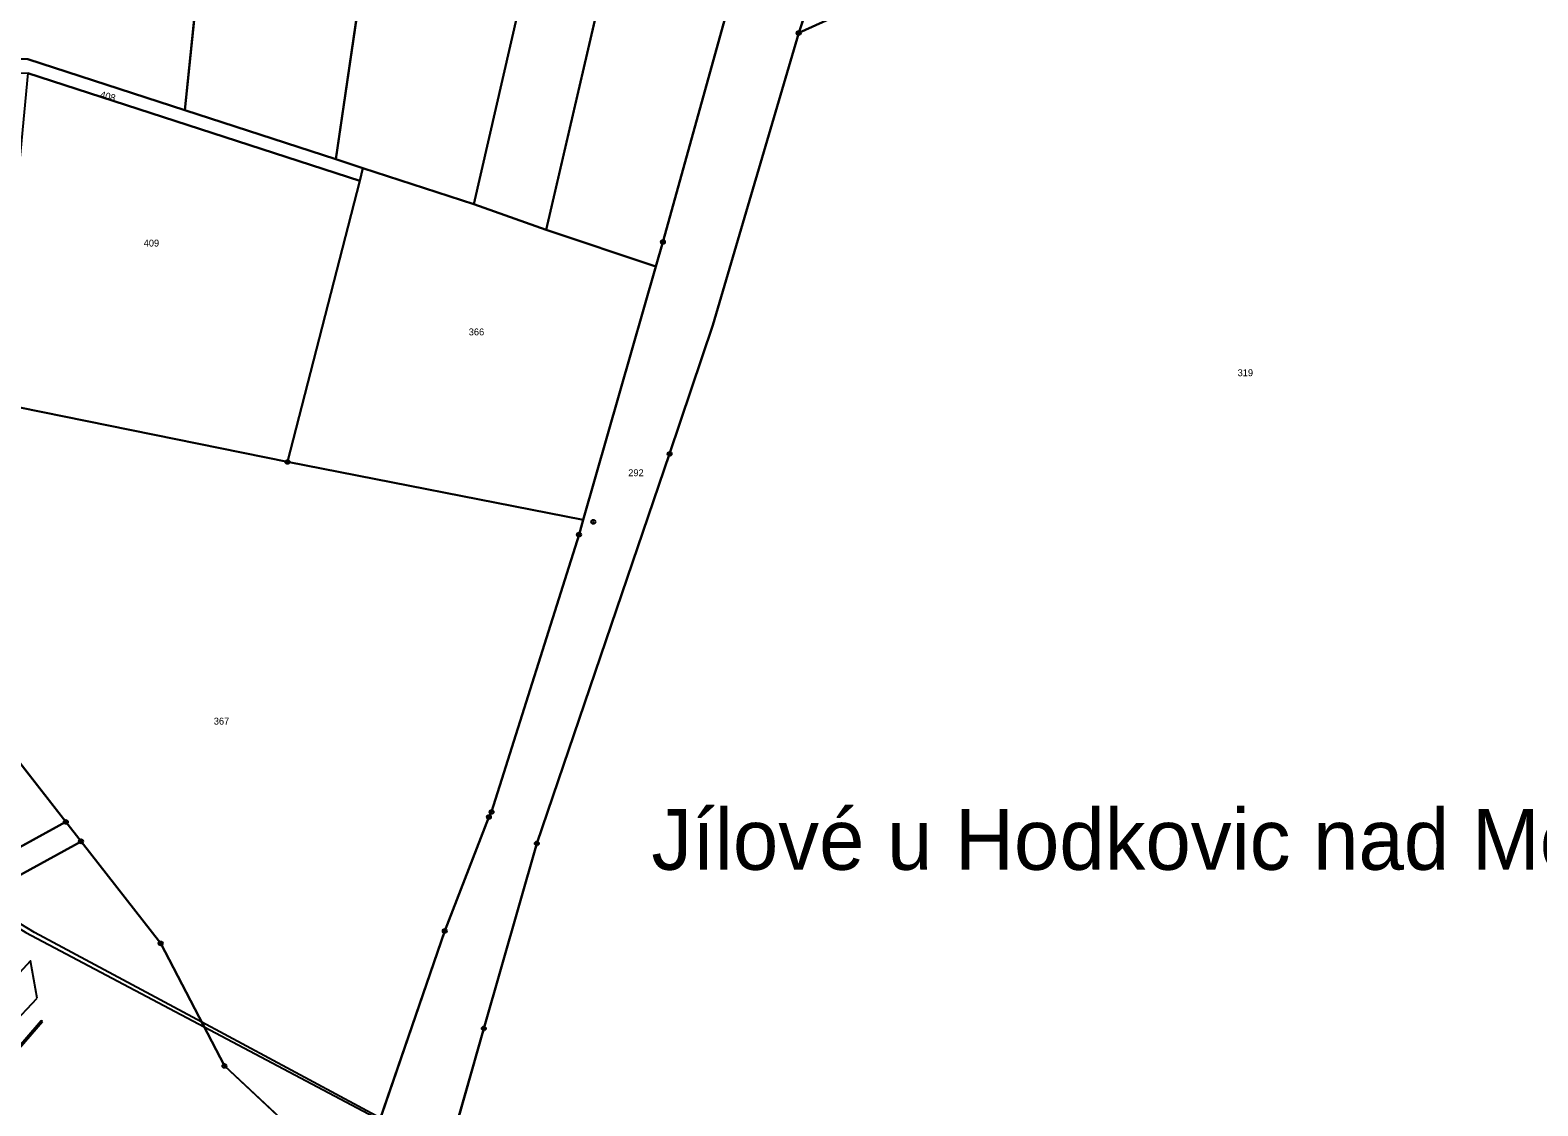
# Model space of a CAD drawing. Extents: x -689422 to -685210, y -987725 to -982160.
# Drawn here: x -686325.7 to -685954.8, y -986505.1 to -986240.3 of the extents above; entities that cross this region are included whole.
import ezdxf

# ---------------------------------------------------------------- set-up
doc = ezdxf.new("R2010")
doc.units = 0
for name, color, linetype in [('KN_Hranice_katastrální území_popis', 7, 'Continuous'), ('KN_Hranice_parcel', 7, 'Continuous'), ('KN_Parcelni cisla', 7, 'Continuous'), ('KN_Polygon parcely', 7, 'Continuous'), ('KN_POZEMKY_ORNA PUDA', 7, 'Continuous'), ('KN_POZEMKY_OSTATNI PLOCHA', 7, 'Continuous'), ('KN_POZEMKY_TTP', 7, 'Continuous'), ('KN_VYUZITI_14_ostatni plocha_dráha', 7, 'Continuous'), ('KN_Věcná břemena k části', 7, 'Continuous'), ('KN_Značky bodu BP', 7, 'Continuous')]:
    doc.layers.add(name, color=color, linetype=linetype)

msp = doc.modelspace()

# ---------------------------------------------------------------- linework, layer by layer
at = {"layer": 'KN_Hranice_parcel'}
for p, q in [((-686095.84, -986117.37), (-686136.64, -986241.02)), ((-686170.02, -986292.49), (-686150.83, -986223.33)), ((-686326.23, -986250.94), (-686244.61, -986277.45)), ((-686250.49, -986272.07), (-686287.61, -986260.01)), ((-686250.49, -986272.07), (-686243.82, -986274.27)), ((-686243.82, -986274.27), (-686244.61, -986277.45)), ((-686216.5, -986283.14), (-686243.82, -986274.27)), ((-686244.61, -986277.45), (-686262.37, -986346.59)), ((-686198.71, -986289.46), (-686216.5, -986283.14)), ((-686171.74, -986298.5), (-686198.71, -986289.46)), ((-686171.74, -986298.5), (-686170.02, -986292.49)), ((-686189.63, -986360.84), (-686171.74, -986298.5)), ((-686333.98, -986332.04), (-686262.37, -986346.59)), ((-686262.37, -986346.59), (-686189.63, -986360.84)), ((-686363.74, -986460.93), (-686316.89, -986435.17)), ((-686316.89, -986435.17), (-686313.16, -986439.96)), ((-686360.85, -986466.19), (-686313.16, -986439.96))]:
    msp.add_line(p, q, dxfattribs=at)
for points in [[(-686287.61, -986260.01), (-686326.21, -986247.46), (-686339.73, -986247.04), (-686323.81, -986199.58), (-686315.21, -986165.49), (-686294.08, -986111.59)], [(-686079.51, -986123.74), (-686120.05, -986233.54), (-686136.64, -986241.02)], [(-686287.61, -986260.01), (-686283.06, -986215.63), (-686271.23, -986167.44), (-686256.35, -986129.53)], [(-686218.39, -986148.4), (-686243.26, -986222.73), (-686250.49, -986272.07)], [(-686182.54, -986165.69), (-686199.37, -986213.85), (-686205.74, -986236.04), (-686216.5, -986283.14)], [(-686166.74, -986173.73), (-686182.84, -986220.79), (-686198.71, -986289.46)], [(-686136.64, -986241.02), (-686157.77, -986312.91), (-686168.38, -986344.61), (-686201.04, -986440.48), (-686214.08, -986486.02), (-686222.26, -986514.82)], [(-686393.73, -986335.43), (-686338.86, -986407.01), (-686316.89, -986435.17)], [(-686189.63, -986360.84), (-686190.67, -986364.48), (-686212.18, -986432.72), (-686212.83, -986433.98), (-686223.69, -986462), (-686245.48, -986525.43)], [(-686313.16, -986439.96), (-686293.56, -986465.08), (-686277.88, -986495.23), (-686245.48, -986525.43)]]:
    msp.add_lwpolyline(points, dxfattribs=at)
at = {"layer": 'KN_Polygon parcely'}
for points in [[(-686256.35, -986129.53), (-686294.08, -986111.59), (-686315.21, -986165.49), (-686323.81, -986199.58), (-686339.73, -986247.04), (-686326.21, -986247.46), (-686287.61, -986260.01), (-686283.06, -986215.63), (-686271.23, -986167.44)], [(-686136.64, -986241.02), (-686120.05, -986233.54), (-686079.51, -986123.74), (-686095.84, -986117.37)], [(-686256.35, -986129.53), (-686271.23, -986167.44), (-686283.06, -986215.63), (-686287.61, -986260.01), (-686250.49, -986272.07), (-686243.26, -986222.73), (-686218.39, -986148.4)], [(-686250.49, -986272.07), (-686243.82, -986274.27), (-686216.5, -986283.14), (-686205.74, -986236.04), (-686199.37, -986213.85), (-686182.54, -986165.69), (-686218.39, -986148.4), (-686243.26, -986222.73)], [(-686205.74, -986236.04), (-686216.5, -986283.14), (-686198.71, -986289.46), (-686182.84, -986220.79), (-686166.74, -986173.73), (-686182.54, -986165.69), (-686199.37, -986213.85)], [(-686166.74, -986173.73), (-686182.84, -986220.79), (-686198.71, -986289.46), (-686171.74, -986298.5), (-686170.02, -986292.49), (-686150.83, -986223.33), (-686158.55, -986214.55), (-686150.96, -986181.1)], [(-686333.98, -986332.04), (-686262.37, -986346.59), (-686244.61, -986277.45), (-686326.23, -986250.94)], [(-686189.63, -986360.84), (-686171.74, -986298.5), (-686198.71, -986289.46), (-686216.5, -986283.14), (-686243.82, -986274.27), (-686244.61, -986277.45), (-686262.37, -986346.59)], [(-686316.89, -986435.17), (-686313.16, -986439.96), (-686293.56, -986465.08), (-686277.88, -986495.23), (-686245.48, -986525.43), (-686223.69, -986462), (-686212.83, -986433.98), (-686212.18, -986432.72), (-686190.67, -986364.48), (-686189.63, -986360.84), (-686262.37, -986346.59), (-686333.98, -986332.04), (-686367.41, -986325.32), (-686369.96, -986327.29), (-686377.99, -986329.38), (-686385.28, -986329.18), (-686393.73, -986335.43), (-686338.86, -986407.01)], [(-686316.89, -986435.17), (-686338.86, -986407.01), (-686393.73, -986335.43), (-686426.63, -986346.03), (-686408.18, -986380.1), (-686363.74, -986460.93)], [(-686360.85, -986466.19), (-686313.16, -986439.96), (-686316.89, -986435.17), (-686363.74, -986460.93)], [(-686268.64, -986613.74), (-686263.17, -986592.87), (-686263.08, -986592.53), (-686245.48, -986525.43), (-686277.88, -986495.23), (-686293.56, -986465.08), (-686313.16, -986439.96), (-686360.85, -986466.19), (-686339.04, -986505.86), (-686281.05, -986622.22)]]:
    msp.add_lwpolyline(points, close=True, dxfattribs=at)
for points in [[(-686222.26, -986514.82), (-686214.08, -986486.02), (-686201.04, -986440.48), (-686168.38, -986344.61), (-686157.77, -986312.91), (-686136.64, -986241.02), (-686095.84, -986117.37)], [(-686328.73, -986199.25), (-686367.73, -986318.6), (-686370.59, -986322.73), (-686377.74, -986326.31), (-686391.61, -986325.86), (-686427.48, -986310.59), (-686454.39, -986299), (-686455.16, -986302.12), (-686392.23, -986329.33), (-686385.28, -986329.18), (-686377.99, -986329.38), (-686369.96, -986327.29), (-686367.41, -986325.32), (-686363.2, -986319.25), (-686341.46, -986252.16), (-686338.9, -986250.37), (-686326.23, -986250.94), (-686244.61, -986277.45), (-686243.82, -986274.27), (-686250.49, -986272.07), (-686287.61, -986260.01), (-686326.21, -986247.46), (-686339.73, -986247.04), (-686323.81, -986199.58)], [(-686150.83, -986223.33), (-686170.02, -986292.49), (-686171.74, -986298.5), (-686189.63, -986360.84), (-686190.67, -986364.48), (-686212.18, -986432.72), (-686212.83, -986433.98), (-686223.69, -986462), (-686245.48, -986525.43), (-686263.08, -986592.53), (-686263.17, -986592.87), (-686268.64, -986613.74), (-686274.17, -986634.95), (-686281.05, -986622.22), (-686281.79, -986632.25), (-686282.71, -986644.54), (-686283.4, -986653.69), (-686317.15, -986737.15), (-686335.84, -986780.59), (-686339.55, -986788.69), (-686341.38, -986792.68), (-686343.41, -986797.11)], [(-686120.05, -986233.54), (-686136.64, -986241.02), (-686157.77, -986312.91), (-686168.38, -986344.61), (-686201.04, -986440.48), (-686214.08, -986486.02), (-686222.26, -986514.82), (-686205.45, -986544.89), (-686181.26, -986594.04), (-686158.28, -986655.04), (-686149.3, -986702.26), (-686138.27, -986745.53), (-686128.64, -986829.8), (-686090.23, -986851.98), (-686084.31, -986849), (-686074.19, -986843.92), (-686054.05, -986878.62), (-686030, -986857.27), (-685896.42, -986709.33)]]:
    msp.add_lwpolyline(points, dxfattribs=at)
at = {"layer": 'KN_POZEMKY_ORNA PUDA'}
for p, q in [((-686287.61, -986260.01), (-686283.06, -986215.63)), ((-686283.06, -986215.63), (-686287.61, -986260.01)), ((-686243.26, -986222.73), (-686250.49, -986272.07)), ((-686250.49, -986272.07), (-686243.26, -986222.73)), ((-686198.71, -986289.46), (-686182.84, -986220.79)), ((-686182.84, -986220.79), (-686198.71, -986289.46)), ((-686150.83, -986223.33), (-686170.02, -986292.49)), ((-686136.64, -986241.02), (-686120.05, -986233.54)), ((-686216.5, -986283.14), (-686205.74, -986236.04)), ((-686205.74, -986236.04), (-686216.5, -986283.14)), ((-686157.77, -986312.91), (-686136.64, -986241.02)), ((-686326.21, -986247.46), (-686287.61, -986260.01)), ((-686287.61, -986260.01), (-686326.21, -986247.46)), ((-686326.23, -986250.94), (-686244.61, -986277.45)), ((-686244.61, -986277.45), (-686326.23, -986250.94)), ((-686250.49, -986272.07), (-686287.61, -986260.01)), ((-686287.61, -986260.01), (-686250.49, -986272.07)), ((-686250.49, -986272.07), (-686243.82, -986274.27)), ((-686243.82, -986274.27), (-686250.49, -986272.07)), ((-686244.61, -986277.45), (-686243.82, -986274.27)), ((-686243.82, -986274.27), (-686244.61, -986277.45)), ((-686243.82, -986274.27), (-686216.5, -986283.14)), ((-686216.5, -986283.14), (-686243.82, -986274.27)), ((-686244.61, -986277.45), (-686262.37, -986346.59)), ((-686262.37, -986346.59), (-686244.61, -986277.45)), ((-686216.5, -986283.14), (-686198.71, -986289.46)), ((-686198.71, -986289.46), (-686216.5, -986283.14)), ((-686171.74, -986298.5), (-686198.71, -986289.46)), ((-686198.71, -986289.46), (-686171.74, -986298.5)), ((-686170.02, -986292.49), (-686171.74, -986298.5)), ((-686171.74, -986298.5), (-686189.63, -986360.84)), ((-686168.38, -986344.61), (-686157.77, -986312.91)), ((-686262.37, -986346.59), (-686333.98, -986332.04)), ((-686333.98, -986332.04), (-686262.37, -986346.59)), ((-686201.04, -986440.48), (-686168.38, -986344.61)), ((-686262.37, -986346.59), (-686189.63, -986360.84)), ((-686189.63, -986360.84), (-686262.37, -986346.59)), ((-686189.63, -986360.84), (-686190.67, -986364.48)), ((-686190.67, -986364.48), (-686212.18, -986432.72)), ((-686338.86, -986407.01), (-686316.89, -986435.17)), ((-686316.89, -986435.17), (-686338.86, -986407.01)), ((-686316.89, -986435.17), (-686363.74, -986460.93)), ((-686363.74, -986460.93), (-686316.89, -986435.17)), ((-686316.89, -986435.17), (-686313.16, -986439.96)), ((-686313.16, -986439.96), (-686316.89, -986435.17)), ((-686212.83, -986433.98), (-686223.69, -986462)), ((-686212.18, -986432.72), (-686212.83, -986433.98)), ((-686360.85, -986466.19), (-686313.16, -986439.96)), ((-686313.16, -986439.96), (-686360.85, -986466.19)), ((-686313.16, -986439.96), (-686293.56, -986465.08)), ((-686293.56, -986465.08), (-686313.16, -986439.96)), ((-686214.08, -986486.02), (-686201.04, -986440.48)), ((-686223.69, -986462), (-686245.48, -986525.43)), ((-686293.56, -986465.08), (-686277.88, -986495.23)), ((-686277.88, -986495.23), (-686293.56, -986465.08)), ((-686222.26, -986514.82), (-686214.08, -986486.02)), ((-686277.88, -986495.23), (-686245.48, -986525.43)), ((-686245.48, -986525.43), (-686277.88, -986495.23))]:
    msp.add_line(p, q, dxfattribs=at)
at = {"layer": 'KN_POZEMKY_OSTATNI PLOCHA'}
for p, q in [((-686095.84, -986117.37), (-686136.64, -986241.02)), ((-686170.02, -986292.49), (-686150.83, -986223.33)), ((-686136.64, -986241.02), (-686157.77, -986312.91)), ((-686171.74, -986298.5), (-686170.02, -986292.49)), ((-686189.63, -986360.84), (-686171.74, -986298.5)), ((-686157.77, -986312.91), (-686168.38, -986344.61)), ((-686168.38, -986344.61), (-686201.04, -986440.48)), ((-686190.67, -986364.48), (-686189.63, -986360.84)), ((-686212.18, -986432.72), (-686190.67, -986364.48)), ((-686223.69, -986462), (-686212.83, -986433.98)), ((-686212.83, -986433.98), (-686212.18, -986432.72)), ((-686201.04, -986440.48), (-686214.08, -986486.02)), ((-686245.48, -986525.43), (-686223.69, -986462)), ((-686214.08, -986486.02), (-686222.26, -986514.82))]:
    msp.add_line(p, q, dxfattribs=at)
at = {"layer": 'KN_POZEMKY_TTP'}
for p, q in [((-686136.64, -986241.02), (-686095.84, -986117.37)), ((-686120.05, -986233.54), (-686136.64, -986241.02))]:
    msp.add_line(p, q, dxfattribs=at)
at = {"layer": 'KN_VYUZITI_14_ostatni plocha_dráha'}
for p, q in [((-686095.84, -986117.37), (-686136.64, -986241.02)), ((-686170.02, -986292.49), (-686150.83, -986223.33)), ((-686136.64, -986241.02), (-686157.77, -986312.91)), ((-686171.74, -986298.5), (-686170.02, -986292.49)), ((-686189.63, -986360.84), (-686171.74, -986298.5)), ((-686157.77, -986312.91), (-686168.38, -986344.61)), ((-686168.38, -986344.61), (-686201.04, -986440.48)), ((-686190.67, -986364.48), (-686189.63, -986360.84)), ((-686212.18, -986432.72), (-686190.67, -986364.48)), ((-686223.69, -986462), (-686212.83, -986433.98)), ((-686212.83, -986433.98), (-686212.18, -986432.72)), ((-686201.04, -986440.48), (-686214.08, -986486.02)), ((-686245.48, -986525.43), (-686223.69, -986462)), ((-686214.08, -986486.02), (-686222.26, -986514.82))]:
    msp.add_line(p, q, dxfattribs=at)
at = {"layer": 'KN_Věcná břemena k části'}
for points in [[(-686282.87, -986485.63), (-686283.47, -986484.47), (-686324.56, -986462.41), (-686382.23, -986427.29), (-686381.47, -986428.69), (-686326.76, -986462.4)], [(-686323.94, -986478.57), (-686325.55, -986469.33), (-686346.58, -986492.14), (-686342.95, -986498.75)], [(-686322.62, -986484.3), (-686322.97, -986484.11), (-686340.06, -986504.01), (-686339.93, -986504.24)], [(-686282.87, -986485.63), (-686239.66, -986508.5), (-686239.52, -986508.08), (-686283.47, -986484.47)]]:
    msp.add_lwpolyline(points, close=True, dxfattribs=at)
at = {"layer": 'KN_Značky bodu BP'}
for centre, radius in [((-686136.64, -986241.02), 0.5), ((-686136.64, -986241.02), 0.0303), ((-686170.02, -986292.49), 0.5), ((-686170.02, -986292.49), 0.0303), ((-686262.37, -986346.59), 0.5), ((-686168.38, -986344.61), 0.5), ((-686168.38, -986344.61), 0.0303), ((-686262.37, -986346.59), 0.0303), ((-686187.15, -986361.33), 0.5), ((-686190.67, -986364.48), 0.5), ((-686190.67, -986364.48), 0.0303), ((-686187.15, -986361.33), 0.0303), ((-686316.89, -986435.17), 0.5), ((-686316.89, -986435.17), 0.0303), ((-686212.83, -986433.98), 0.5), ((-686212.83, -986433.98), 0.0303), ((-686212.18, -986432.72), 0.5), ((-686212.18, -986432.72), 0.0303), ((-686313.16, -986439.96), 0.5), ((-686313.16, -986439.96), 0.0303), ((-686201.04, -986440.48), 0.5), ((-686201.04, -986440.48), 0.0303), ((-686293.56, -986465.08), 0.5), ((-686223.69, -986462), 0.5), ((-686223.69, -986462), 0.0303), ((-686293.56, -986465.08), 0.0303), ((-686214.08, -986486.02), 0.5), ((-686214.08, -986486.02), 0.0303), ((-686277.88, -986495.23), 0.5), ((-686277.88, -986495.23), 0.0303)]:
    msp.add_circle(centre, radius, dxfattribs=at)

# ---------------------------------------------------------------- texts
at = {"layer": 'KN_Hranice_katastrální území_popis'}
msp.add_text('Jílové u Hodkovic nad Mohelkou 603414', height=15, dxfattribs=at).set_placement((-686172.87, -986446.96))
at = {"layer": 'KN_Parcelni cisla'}
msp.add_text('408', height=1.7, rotation=345, dxfattribs=at).set_placement((-686308.6, -986256.93))
for s, p in [('409', (-686297.74, -986293.59)), ('366', (-686217.79, -986315.45)), ('319', (-686028.67, -986325.49)), ('292', (-686178.56, -986350.11)), ('367', (-686280.5, -986411.23))]:
    msp.add_text(s, height=1.7, dxfattribs=at).set_placement(p)

doc.saveas('drawing.dxf')
